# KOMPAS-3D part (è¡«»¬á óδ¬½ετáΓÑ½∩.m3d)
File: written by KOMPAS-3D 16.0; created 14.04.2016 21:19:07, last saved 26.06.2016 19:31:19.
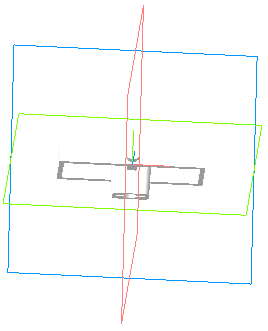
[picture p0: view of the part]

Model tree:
1. Эскиз:1
2. Операция выдавливания:1
     Расстояние 1 = 4
3. Скругление:1
     Радиус = 2
4. Скругление:2
     Радиус = 1
5. Оболочка:1
     Толщина стенки 2 = 1
6. Эскиз:2
7. Операция выдавливания:2
     Расстояние 1 = 9.91899; Угол 1 = 4; Расстояние 2 = 5; Угол 2 = 2
8. Скругление:3
     Радиус = 1
9. Эскиз:3
10. Вырезать элемент выдавливания:1
     Расстояние 1 = 10
11. Скругление:4
     Радиус = 0.2
12. Эскиз:4
13. Операция выдавливания:3
     Расстояние 1 = 9.91899; Расстояние 2 = 5; Угол 2 = 2
14. Операция выдавливания:4
     Расстояние 1 = 7.24318; Расстояние 2 = 5; Угол 2 = 2
15. Операция выдавливания:5
     Расстояние 1 = 7.23196; Расстояние 2 = 5; Угол 2 = 2
16. Эскиз:5
17. Операция выдавливания:6
     Расстояние 1 = 1.5; Расстояние 2 = 5; Угол 2 = 2
18. Эскиз:6
19. Операция выдавливания:7
     Расстояние 1 = 1.5; Расстояние 2 = 5; Угол 2 = 2
20. Эскиз:7
21. Операция выдавливания:8
     Расстояние 1 = 0.3; Расстояние 2 = 5; Угол 2 = 2
22. Скругление:5
     Радиус = 0.5
23. Эскиз:8
24. Вырезать элемент выдавливания:2
     Расстояние 1 = 0.2
25. Скругление:6
     Радиус = 0.1
26. Эскиз:9
27. Операция выдавливания:9
     Расстояние 1 = 0.3; Расстояние 2 = 5; Угол 2 = 2
28. Скругление:7
     Радиус = 0.1
29. Эскиз:10
30. Вырезать элемент выдавливания:3
     Расстояние 1 = 0.2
